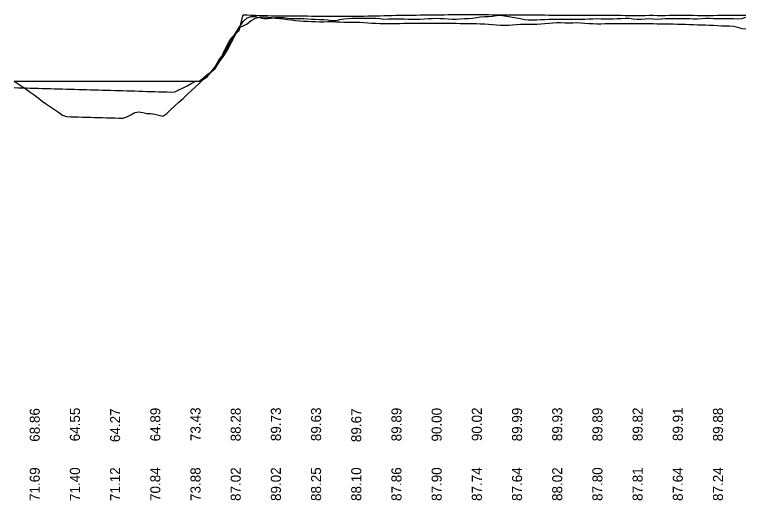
# Model space of a CAD drawing. Extents: x 2147288 to 2220488, y 740833 to 759333.
# Drawn here: x 2199799 to 2200708, y 750179 to 750784 of the extents above; entities that cross this region are included whole.
import ezdxf

# ---------------------------------------------------------------- set-up
doc = ezdxf.new("R2010")
doc.units = 0
doc.layers.add('RD_DDB_Profile_EX', color=7, linetype='Continuous')
doc.layers.add('RD_DDB_StripGrade', color=7, linetype='Continuous')

msp = doc.modelspace()

# ---------------------------------------------------------------- linework, layer by layer
at = {"layer": 'RD_DDB_Profile_EX'}
for points in [[(2200038.28, 750707.22), (2200043.28, 750711.79), (2200048.28, 750716.61), (2200053.28, 750724.79), (2200058.28, 750735.12), (2200063.28, 750745.44), (2200068.28, 750754.47), (2200073.28, 750759.12), (2200078.28, 750763.78), (2200083.28, 750783.48), (2200088.28, 750783.25), (2200093.28, 750783.03), (2200098.28, 750782.8), (2200103.28, 750782.58), (2200108.28, 750782.42), (2200113.28, 750782.33), (2200118.28, 750782.25), (2200123.28, 750782.16), (2200128.28, 750782.08), (2200133.28, 750782.08), (2200138.28, 750782.05), (2200143.28, 750782.03), (2200148.28, 750782.01), (2200153.28, 750781.98), (2200158.28, 750781.93), (2200163.28, 750781.87), (2200168.28, 750781.79), (2200173.28, 750781.71), (2200178.28, 750781.64), (2200183.28, 750781.54), (2200188.28, 750781.55), (2200193.28, 750781.57), (2200198.28, 750781.58), (2200203.28, 750781.57), (2200208.28, 750781.53), (2200213.28, 750781.5), (2200218.28, 750781.51), (2200223.28, 750781.6), (2200228.28, 750781.7), (2200233.28, 750781.8), (2200238.28, 750781.9), (2200243.28, 750781.99), (2200248.28, 750782.08), (2200253.28, 750782.18), (2200258.28, 750782.31), (2200263.28, 750782.44), (2200268.28, 750782.57), (2200273.28, 750782.69), (2200278.28, 750782.81), (2200283.28, 750782.93), (2200288.28, 750783.05), (2200293.28, 750783.07), (2200298.28, 750783.08), (2200303.28, 750783.13), (2200308.28, 750783.21), (2200313.28, 750783.3), (2200318.28, 750783.36), (2200323.28, 750783.39), (2200328.28, 750783.41), (2200333.28, 750783.48), (2200338.28, 750783.53), (2200343.28, 750783.55), (2200348.28, 750783.56), (2200353.28, 750783.58), (2200358.28, 750783.58), (2200363.28, 750783.56), (2200368.28, 750783.53), (2200373.28, 750783.54), (2200378.28, 750783.53), (2200383.28, 750783.52), (2200388.28, 750783.52), (2200393.28, 750783.51), (2200398.28, 750783.49), (2200403.28, 750783.46), (2200408.28, 750783.43), (2200413.28, 750783.42), (2200418.28, 750783.4), (2200423.28, 750783.38), (2200428.28, 750783.37), (2200433.28, 750783.34), (2200438.28, 750783.29), (2200443.28, 750783.24), (2200448.28, 750783.2), (2200453.28, 750783.17), (2200458.28, 750783.12), (2200463.28, 750783.1), (2200468.28, 750783.09), (2200473.28, 750783.08), (2200478.28, 750783.07), (2200483.28, 750783.08), (2200488.28, 750783.09), (2200493.28, 750783.09), (2200498.28, 750783.09), (2200503.28, 750783.09), (2200508.28, 750783.08), (2200513.28, 750783.07), (2200518.28, 750783.03), (2200523.28, 750782.96), (2200528.28, 750782.88), (2200533.28, 750782.85), (2200538.28, 750782.8)], [(2200038.28, 750706.34), (2200043.28, 750712.45), (2200048.28, 750716.73), (2200053.28, 750724.28), (2200058.28, 750731.06), (2200063.28, 750738.78), (2200068.28, 750748.37), (2200073.28, 750758.13), (2200078.28, 750767.34), (2200083.28, 750775), (2200088.28, 750779.59), (2200093.28, 750781.41), (2200098.28, 750781.12), (2200103.28, 750780.1), (2200108.28, 750778.95), (2200113.28, 750778.67), (2200118.28, 750779.21), (2200123.28, 750780), (2200128.28, 750779.8), (2200133.28, 750779.82), (2200138.28, 750779.31), (2200143.28, 750778.93), (2200148.28, 750778.86), (2200153.28, 750778.7), (2200158.28, 750778.55), (2200163.28, 750778.36), (2200168.28, 750778.06), (2200173.28, 750777.73), (2200178.28, 750777.65), (2200183.28, 750777.41), (2200188.28, 750777.22), (2200193.28, 750776.45), (2200198.28, 750776.43), (2200203.28, 750777.66), (2200208.28, 750778.27), (2200213.28, 750778.75), (2200218.28, 750779.23), (2200223.28, 750779.36), (2200228.28, 750779.33), (2200233.28, 750779.28), (2200238.28, 750779.26), (2200243.28, 750779.26), (2200248.28, 750779.27), (2200253.28, 750778.63), (2200258.28, 750777.91), (2200263.28, 750778.14), (2200268.28, 750778.33), (2200273.28, 750778.52), (2200278.28, 750778.46), (2200283.28, 750778.21), (2200288.28, 750777.96), (2200293.28, 750777.71), (2200298.28, 750777.74), (2200303.28, 750778.01), (2200308.28, 750778.28), (2200313.28, 750778.54), (2200318.28, 750778.81), (2200323.28, 750779.22), (2200328.28, 750778.94), (2200333.28, 750778.65), (2200338.28, 750778.36), (2200343.28, 750777.77), (2200348.28, 750778.04), (2200353.28, 750778.32), (2200358.28, 750778.59), (2200363.28, 750778.87), (2200368.28, 750779.3), (2200373.28, 750780.16), (2200378.28, 750780.82), (2200383.28, 750781.31), (2200388.28, 750781.44), (2200393.28, 750781.57), (2200398.28, 750782.28), (2200403.28, 750783.01), (2200408.28, 750782.16), (2200413.28, 750781.29), (2200418.28, 750780.39), (2200423.28, 750779.48), (2200428.28, 750778.58), (2200433.28, 750777.68), (2200438.28, 750777), (2200443.28, 750776.97), (2200448.28, 750777.17), (2200453.28, 750777.37), (2200458.28, 750777.57), (2200463.28, 750777.77), (2200468.28, 750778), (2200473.28, 750777.9), (2200478.28, 750777.88), (2200483.28, 750777.86), (2200488.28, 750777.84), (2200493.28, 750777.82), (2200498.28, 750777.8), (2200503.28, 750777.91), (2200508.28, 750778.1), (2200513.28, 750778.29), (2200518.28, 750778.48), (2200523.28, 750778.66), (2200528.28, 750778.48), (2200533.28, 750778.31), (2200538.28, 750778.15)], [(2200538.28, 750782.8), (2200543.28, 750782.78), (2200548.28, 750782.76), (2200553.28, 750782.74), (2200558.28, 750782.61), (2200563.28, 750782.47), (2200568.28, 750782.32), (2200573.28, 750782.3), (2200578.28, 750782.43), (2200583.28, 750782.58), (2200588.28, 750782.69), (2200593.28, 750782.69), (2200598.28, 750782.68), (2200603.28, 750782.67), (2200608.28, 750782.67), (2200613.28, 750782.79), (2200618.28, 750782.91), (2200623.28, 750783.01), (2200628.28, 750782.98), (2200633.28, 750782.96), (2200638.28, 750782.94), (2200643.28, 750782.82), (2200648.28, 750782.68), (2200653.28, 750782.6), (2200658.28, 750782.6), (2200663.28, 750782.63), (2200668.28, 750782.66), (2200673.28, 750782.7), (2200678.28, 750782.8), (2200683.28, 750782.89), (2200688.28, 750782.95), (2200693.28, 750782.96), (2200698.28, 750782.95), (2200703.28, 750782.93), (2200708.28, 750782.92)], [(2200038.28, 750708.91), (2200043.28, 750712.44), (2200048.28, 750718.77), (2200053.28, 750727.73), (2200058.28, 750733.39), (2200063.28, 750742.36), (2200068.28, 750752.11), (2200073.28, 750759.83), (2200078.28, 750767.36), (2200083.28, 750769.46), (2200088.28, 750772.12), (2200093.28, 750776.12), (2200098.28, 750779.17), (2200103.28, 750780.22), (2200108.28, 750780.79), (2200113.28, 750780.38), (2200118.28, 750779.9), (2200123.28, 750779.33), (2200128.28, 750778.9), (2200133.28, 750778.23), (2200138.28, 750777.56), (2200143.28, 750776.89), (2200148.28, 750776.26), (2200153.28, 750775.69), (2200158.28, 750775.42), (2200163.28, 750775.28), (2200168.28, 750775.16), (2200173.28, 750774.99), (2200178.28, 750774.74), (2200183.28, 750774.62), (2200188.28, 750774.9), (2200193.28, 750775.1), (2200198.28, 750774.78), (2200203.28, 750774.44), (2200208.28, 750774.33), (2200213.28, 750774.22), (2200218.28, 750774.1), (2200223.28, 750774.06), (2200228.28, 750773.98), (2200233.28, 750773.86), (2200238.28, 750773.37), (2200243.28, 750773.03), (2200248.28, 750772.84), (2200253.28, 750772.73), (2200258.28, 750772.68), (2200263.28, 750772.64), (2200268.28, 750772.6), (2200273.28, 750772.65), (2200278.28, 750772.66), (2200283.28, 750772.8), (2200288.28, 750772.9), (2200293.28, 750772.94), (2200298.28, 750773.01), (2200303.28, 750773.08), (2200308.28, 750773.08), (2200313.28, 750773.1), (2200318.28, 750773.12), (2200323.28, 750773.1), (2200328.28, 750772.94), (2200333.28, 750772.91), (2200338.28, 750772.85), (2200343.28, 750772.84), (2200348.28, 750772.83), (2200353.28, 750772.7), (2200358.28, 750772.49), (2200363.28, 750772.39), (2200368.28, 750772.46), (2200373.28, 750772.5), (2200378.28, 750772.26), (2200383.28, 750772.01), (2200388.28, 750771.73), (2200393.28, 750771.31), (2200398.28, 750770.88), (2200403.28, 750770.64), (2200408.28, 750770.55), (2200413.28, 750770.54), (2200418.28, 750770.86), (2200423.28, 750771.19), (2200428.28, 750771.51), (2200433.28, 750771.69), (2200438.28, 750771.64), (2200443.28, 750771.73), (2200448.28, 750771.81), (2200453.28, 750772.2), (2200458.28, 750772.35), (2200463.28, 750772.83), (2200468.28, 750773.31), (2200473.28, 750773.67), (2200478.28, 750773.59), (2200483.28, 750773.51), (2200488.28, 750773.42), (2200493.28, 750773.48), (2200498.28, 750773.58), (2200503.28, 750773.23), (2200508.28, 750772.78), (2200513.28, 750772.57), (2200518.28, 750772.37), (2200523.28, 750772.16), (2200528.28, 750772.27), (2200533.28, 750772.54), (2200538.28, 750772.51)], [(2200538.28, 750778.15), (2200543.28, 750778.35), (2200548.28, 750778.6), (2200553.28, 750778.84), (2200558.28, 750779.09), (2200563.28, 750779), (2200568.28, 750778.53), (2200573.28, 750777.94), (2200578.28, 750777.94), (2200583.28, 750778.38), (2200588.28, 750778.55), (2200593.28, 750778.39), (2200598.28, 750778.04), (2200603.28, 750778.5), (2200608.28, 750778.86), (2200613.28, 750778.75), (2200618.28, 750778.88), (2200623.28, 750778.7), (2200628.28, 750778.66), (2200633.28, 750778.68), (2200638.28, 750778.6), (2200643.28, 750778.33), (2200648.28, 750778.41), (2200653.28, 750778.93), (2200658.28, 750779), (2200663.28, 750779.03), (2200668.28, 750778.93), (2200673.28, 750778.83), (2200678.28, 750778.76), (2200683.28, 750778.77), (2200688.28, 750778.8), (2200693.28, 750778.61), (2200698.28, 750778.31), (2200703.28, 750778.75), (2200708.28, 750780.34)], [(2200538.28, 750772.51), (2200543.28, 750772.49), (2200548.28, 750772.47), (2200553.28, 750772.48), (2200558.28, 750772.51), (2200563.28, 750772.53), (2200568.28, 750772.55), (2200573.28, 750772.56), (2200578.28, 750772.55), (2200583.28, 750772.46), (2200588.28, 750772.45), (2200593.28, 750772.4), (2200598.28, 750772.3), (2200603.28, 750772.2), (2200608.28, 750772.1), (2200613.28, 750772.01), (2200618.28, 750771.94), (2200623.28, 750771.83), (2200628.28, 750771.7), (2200633.28, 750771.56), (2200638.28, 750771.34), (2200643.28, 750771.13), (2200648.28, 750771.03), (2200653.28, 750770.86), (2200658.28, 750770.69), (2200663.28, 750770.56), (2200668.28, 750770.27), (2200673.28, 750769.96), (2200678.28, 750769.57), (2200683.28, 750769.7), (2200688.28, 750769.62), (2200693.28, 750769.11), (2200698.28, 750767.88), (2200703.28, 750766.38), (2200708.28, 750765.76)], [(2199798.28, 750692.8), (2199803.28, 750692.66), (2199808.28, 750692.52), (2199813.28, 750692.37), (2199818.28, 750692.23), (2199823.28, 750692.09), (2199828.28, 750691.95), (2199833.28, 750691.81), (2199838.28, 750691.66), (2199843.28, 750691.52), (2199848.28, 750691.38), (2199853.28, 750691.24), (2199858.28, 750691.1), (2199863.28, 750690.95), (2199868.28, 750690.81), (2199873.28, 750690.67), (2199878.28, 750690.53), (2199883.28, 750690.39), (2199888.28, 750690.24), (2199893.28, 750690.1), (2199898.28, 750689.96), (2199903.28, 750689.82), (2199908.28, 750689.68), (2199913.28, 750689.54), (2199918.28, 750689.39), (2199923.28, 750689.25), (2199928.28, 750689.11), (2199933.28, 750688.97), (2199938.28, 750688.83), (2199943.28, 750688.68), (2199948.28, 750688.54), (2199953.28, 750688.4), (2199958.28, 750688.26), (2199963.28, 750688.12), (2199968.28, 750687.97), (2199973.28, 750687.83), (2199978.28, 750687.69), (2199983.28, 750687.55), (2199988.28, 750687.41), (2199993.28, 750687.26), (2199998.28, 750687.38), (2200003.28, 750689.93), (2200008.28, 750692.51), (2200013.28, 750695.09), (2200018.28, 750697.67), (2200023.28, 750700.25), (2200028.28, 750700.75), (2200033.28, 750704.46), (2200038.28, 750708.91)], [(2199798.28, 750700.87), (2199803.28, 750697.55), (2199808.28, 750694.11), (2199813.28, 750690.68), (2199818.28, 750687.25), (2199823.28, 750683.82), (2199828.28, 750679.95), (2199833.28, 750676.02), (2199838.28, 750672.33), (2199843.28, 750668.77), (2199848.28, 750665.39), (2199853.28, 750662.01), (2199858.28, 750658.63), (2199863.28, 750656.68), (2199868.28, 750656.54), (2199873.28, 750656.4), (2199878.28, 750656.26), (2199883.28, 750656.12), (2199888.28, 750655.98), (2199893.28, 750655.83), (2199898.28, 750655.69), (2199903.28, 750655.55), (2199908.28, 750655.41), (2199913.28, 750655.27), (2199918.28, 750655.12), (2199923.28, 750654.98), (2199928.28, 750654.84), (2199933.28, 750654.7), (2199938.28, 750656.49), (2199943.28, 750659.07), (2199948.28, 750661.65), (2199953.28, 750662.74), (2199958.28, 750661.66), (2199963.28, 750660.58), (2199968.28, 750660.37), (2199973.28, 750659.61), (2199978.28, 750658.51), (2199983.28, 750657.41), (2199988.28, 750660.72), (2199993.28, 750665.38), (2199998.28, 750670.04), (2200003.28, 750674.69), (2200008.28, 750679.35), (2200013.28, 750684.01), (2200018.28, 750688.67), (2200023.28, 750693.32), (2200028.28, 750697.98), (2200033.28, 750702.64), (2200038.28, 750707.22)], [(2199798.28, 750700.75), (2199803.28, 750700.75), (2199808.28, 750700.75), (2199813.28, 750700.75), (2199818.28, 750700.75), (2199823.28, 750700.75), (2199828.28, 750700.75), (2199833.28, 750700.75), (2199838.28, 750700.75), (2199843.28, 750700.75), (2199848.28, 750700.75), (2199853.28, 750700.75), (2199858.28, 750700.75), (2199863.28, 750700.75), (2199868.28, 750700.75), (2199873.28, 750700.75), (2199878.28, 750700.75), (2199883.28, 750700.75), (2199888.28, 750700.75), (2199893.28, 750700.75), (2199898.28, 750700.75), (2199903.28, 750700.75), (2199908.28, 750700.75), (2199913.28, 750700.75), (2199918.28, 750700.75), (2199923.28, 750700.75), (2199928.28, 750700.75), (2199933.28, 750700.75), (2199938.28, 750700.75), (2199943.28, 750700.75), (2199948.28, 750700.75), (2199953.28, 750700.75), (2199958.28, 750700.75), (2199963.28, 750700.75), (2199968.28, 750700.75), (2199973.28, 750700.75), (2199978.28, 750700.75), (2199983.28, 750700.75), (2199988.28, 750700.75), (2199993.28, 750700.75), (2199998.28, 750700.75), (2200003.28, 750700.75), (2200008.28, 750700.75), (2200013.28, 750700.75), (2200018.28, 750700.75), (2200023.28, 750700.75), (2200028.28, 750700.75), (2200033.28, 750702.78), (2200038.28, 750706.34)]]:
    msp.add_lwpolyline(points, dxfattribs=at)

# ---------------------------------------------------------------- texts
for s, p in [('68.86', (2199830.08, 750252.13)), ('64.55', (2199880.08, 750252.69)), ('64.27', (2199930.08, 750251.67)), ('64.89', (2199980.08, 750252.64)), ('73.43', (2200030.08, 750252.89)), ('88.28', (2200080.08, 750252.64)), ('89.73', (2200130.08, 750252.89)), ('89.63', (2200180.08, 750252.89)), ('89.67', (2200230.08, 750251.67)), ('89.89', (2200280.08, 750252.64)), ('90.00', (2200330.08, 750252.38)), ('90.02', (2200380.08, 750252.89)), ('89.99', (2200430.08, 750252.64)), ('89.93', (2200480.08, 750252.89)), ('89.89', (2200530.08, 750252.64)), ('89.82', (2200580.08, 750252.89)), ('89.91', (2200630.08, 750253)), ('89.88', (2200680.08, 750252.64))]:
    msp.add_text(s, height=12.5, rotation=90, dxfattribs=at).set_placement(p)
at = {"layer": 'RD_DDB_StripGrade'}
for s, p in [('71.69', (2199830.08, 750178.43)), ('71.40', (2199880.08, 750178.43)), ('71.12', (2199930.08, 750178.43)), ('70.84', (2199980.08, 750178.43)), ('73.88', (2200030.08, 750178.43)), ('87.02', (2200080.08, 750178.43)), ('89.02', (2200130.08, 750178.43)), ('88.25', (2200180.08, 750178.43)), ('88.10', (2200230.08, 750178.43)), ('87.86', (2200280.08, 750178.43)), ('87.90', (2200330.08, 750178.43)), ('87.74', (2200380.08, 750178.43)), ('87.64', (2200430.08, 750178.43)), ('88.02', (2200480.08, 750178.43)), ('87.80', (2200530.08, 750178.43)), ('87.81', (2200580.08, 750178.43)), ('87.64', (2200630.08, 750178.43)), ('87.24', (2200680.08, 750178.43))]:
    msp.add_text(s, height=12.5, rotation=90, dxfattribs=at).set_placement(p)

doc.saveas('drawing.dxf')
